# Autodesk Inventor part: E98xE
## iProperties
Author: Administrator
Shininess: 47.0
PropertySet Name: _Private Model Information
Created: 2001-03
Part Number: E98xE
Description: Conduit Body Covewr, PVC, E98xE
Document SubType Name: Modeling
Designer: Administrator
Material: PVC-Piping
Control State: 0
Master: False
Checked Out: False
PropertySet Name: Design Tracking Control
Density: 1.4
Volumn: 351.4714011146463
Area: 854.0499316481936
PropertySet Name: Model Information
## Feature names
1. Base [Extrusion]
2. Extrusion14
3. Extrusion16
4. Extrusion17
5. Extrusion19
6. Extrusion20
